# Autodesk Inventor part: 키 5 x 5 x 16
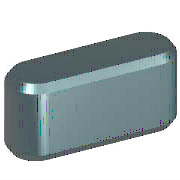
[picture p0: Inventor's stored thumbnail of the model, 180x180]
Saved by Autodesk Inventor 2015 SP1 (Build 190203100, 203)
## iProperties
IsCustomPart: 1
Created: 2012-02
Part Number: 키 5 x 5 x 16
Material: 강철, 연강
Description: 키 및 해당 키홈
Document SubType Name: Modeling
Standard: KS B 1311
Designer: mduedu
Standards Organization: KS
Language: ko-KR
Size Designation: 5 x 5 x 16
Categories: <MemberInstance><Categories><Category DisplayName="샤프트 부품" InternalName="7f7aeb1f-a693-4053-b835-cee3144e0d98" Mnemonic="SHFT"><Category DisplayName="키" Interna
Density: 1 g/cm^3
Appearance: 노란색
Author: mduedu
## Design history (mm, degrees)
workplane "Work Plane1"
workplane "Work Plane2"
sketch "스케치1"
  geometry: L1 (2.5, 2.5)-(13.5, 2.5); L2 (13.5, -2.5)-(2.5, -2.5); L3 (0, 9.4)-(0, -7.4) reference; L4 (-5, 0)-(30, 0) reference; L5 (16, 0)-(16, 7); A1 r 2.5 centre (2.5, 0) between (2.5, 2.5) and (2.5, -2.5); A2 r 2.5 centre (13.5, 0) between (13.5, -2.5) and (13.5, 2.5)
  constraints: 6 end point, 5 point on circle, 4 tangent, 3 point on line, 2 centre point, 1 horizontal, 1 parallel, 1 perpendicular
  dimensions: "d0" = 2.5 radius of A1 (= 0.5 x PB); "d13" = 2.5 radius of A2 (= 0.5 x PB); "d14" = 16 distance between parallel lines of L5 L3 (= NLG)
extrude "본체1" new body sketch "스케치1" taper "d3" = 0 deg; stored distance "d4" = 10
workplane "Work Plane3"
body "Solid1"
chamfer "모따기1" distance "d8" = 0.4 (= PHH); stored, may be unused: second distance "d9" = 0.4 (= PHH), angle "d15" = 45 deg
other parameters: "d1" = -3 (= -PNT), "d2" = 2 (= PH - PNT), "NLG" = 16 [user parameter; used in 3 equation terms], "PB" = 5 [user parameter; used in 2 equation terms], "PNT" = 3 [user parameter; used in 2 equation terms], "PH" = 5 [user parameter; used in 1 equation term], "PHH" = 0.4 [user parameter; used in 2 equation terms], "d10" = 0, "d16" = 0, "d17" = 0, "d18" = 0, "WDMIN" = 12 [user parameter], "PLB2" = 16 (= NLG) [user parameter], "WDMAX" = 17 [user parameter], "PLB1" = 16 (= NLG) [user parameter], "RR" = 0.16 [user parameter], "PUEB" = 2.3 [user parameter]
